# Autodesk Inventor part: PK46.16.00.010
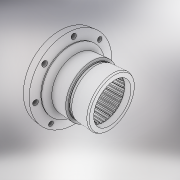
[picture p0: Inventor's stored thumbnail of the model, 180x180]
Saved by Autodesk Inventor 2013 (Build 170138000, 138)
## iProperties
Shininess: 25.0
Length Units: 11269
Angle Units: 11279
Time Units: 11290
Mass Units: 11283
Length Display Precision: 3
Angle Display Precision: 2
Created: 2001-08
Part Number: PK46.16.00.010
Material: Steel, Mild
Document SubType Name: Modeling
Designer: SOleg
Density: 7.86 g/cm^3
Mass: 4404.42 g
Surface Area: 1072.64 cm^2
Volume: 560.359 cm^3
Density: 0.0
Volumn: 0.0
Area: 0.0
PropertySet Name: Model Information
Control State: 0
Master: False
Checked Out: False
Checked Out Date: 2008-10-09
Last Check In Date: 2008-10-09
Author: SOleg
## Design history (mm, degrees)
sketch "Sketch1"
  geometry: L1 (45, 40)-(45, 48.268); L2 (33, 40)-(45, 40); L3 (33, 40.5)-(33, 40); L4 (-22, 40.5)-(33, 40.5); L5 (-22, 35)-(-22, 40.5); L6 (-26, 35)-(-22, 35); L7 (-26, 40)-(-26, 35); L8 (-33, 40)-(-26, 40); L9 (-33, 35)-(-33, 40); L10 (-40, 35)-(-33, 35); L11 (-40, 45)-(-40, 35); L12 (-45, 45)-(-40, 45); L13 (-45, 55)-(-45, 45); L14 (7, 55)-(-45, 55); L15 (7, 49)-(7, 55); L16 (12, 49)-(7, 49); L17 (12, 50)-(12, 49); L18 (42, 50)-(12, 50); L19 (45, 48.268)-(42, 50); L20 (-45, 0)-(45, 0); L21 (-45, 0)-(45, 0)
  constraints: 42 end point, 10 horizontal, 9 vertical, 2 collinear, 1 other
  dimensions: "d1" = 50 vertical distance of L18.start L20.end; "d3" = 40 distance of L1.start L20.end; "d5" = 40.5 vertical distance of L3.start L20.end; "d7" = 35 vertical distance of L5.start L20.start; "d9" = 45 vertical distance of L11.start L20.start; "d11" = 55 distance of L13.start L20.start; "d13" = 67 horizontal distance of L4.start L1.end; "d15" = 12 distance of L2.start L1.start; "d17" = 5 distance of L16.start L15.start; "d19" = 90 horizontal distance of L1.start L12.start; "d23" = 18 horizontal distance of L4.start L10.start; "d25" = 7 distance of L8.start L7.start; "d27" = 7 distance of L10.start L9.start; "d29" = 30 deg angle of L18 L19; "d31" = 3 horizontal distance of L1.end L18.start; "d33" = 49 vertical distance of L16.start L20.end; "d90" = 38 distance between parallel lines of L15 L1
revolve "RevolutionFull1" sketch "Sketch1" stored, may be unused: angle "d34" = 360 deg
workplane "Work Plane1"
node "WorkPlane1"
sketch "Sketch2"
  geometry: L1 (-41.54, -4.27)-(-37.25, -1.145); L2 (-41.54, 4.27)-(-41.54, -4.27); L3 (-37.25, 1.145)-(-41.54, 4.27); L4 (-37.25, -1.145)-(-37.25, 1.145); C1 r 55 at (0, 0) reference; C2 r 35 at (0, 0) reference
  constraints: 8 end point, 2 vertical
  dimensions: "d41" = 8.54 distance of L2.start L1.start; "d43" = 2.29 distance of L1.end L3.start; "d45" = 4.29 horizontal distance of L3.start L2.start; "d47" = 4.27 vertical distance of L1.start C1.centre; "d49" = 1.145 vertical distance of L1.end C2.centre; "d51" = 37.25 horizontal distance of L3.start C2.centre
extrude "ExtrusionBlind1" join sketch "Sketch2" distance "d52" = 55; taper "d53" = 0 deg
node "WorkPlane2"
node "WorkPlane3"
sketch "Sketch3"
  geometry: L1 (18.5, -87.5)-(18.5, -67.5); L2 (32.5, -87.5)-(18.5, -87.5); L3 (32.5, -67.5)-(32.5, -87.5); L4 (28.5, -67.5)-(32.5, -67.5); L5 (28.5, -55)-(28.5, -67.5); L6 (9.283, -55)-(28.5, -55); L7 (16.5, -67.5)-(9.283, -55); L8 (28.5, 45)-(28.5, -45) reference; L9 (23.5, 35)-(23.5, -35) reference; L10 (-184.647, 0)-(153.932, 0); L11 (-61.5, 48.268)-(-61.5, -48.268) reference; L12 (28.5, 55)-(28.5, -55) reference; L13 (28.5, -55)-(-23.5, -55) reference; L14 (28.5, 0)-(80.478, 0); L15 (28.5, -55)-(28.5, -55); L16 (16.5, -67.5)-(18.5, -67.5); L17 (16.5, -67.5)-(18.5, -67.5); L18 (9.283, -55)-(28.5, -55)
  constraints: 27 end point, 3 collinear, 3 horizontal, 3 parallel, 3 vertical, 1 midpoint, 1 perpendicular
  dimensions: "d66" = 14 distance of L2.start L1.start; "d91" = 175 diameter of L2 L10; "d92" = 135 diameter of L4 L10; "d93" = 94 distance between parallel lines of L3 L11; "d94" = 2 distance of L7.start L1.end; "d95" = 135 diameter of L16 L10; "d99" = 4 distance of L4.start L3.start; "d100" = 60 deg angle of L7 L13
revolve "RevolutionAngle1" sketch "Sketch3" stored, may be unused: angle "d69" = 360 deg
workaxis "Work Axis2"
sketch "Sketch7"
  geometry: C1 r 87.5 at (0, 0) reference; C2 r 5 at (0, 77.5)
  constraints: 1 centre point
  dimensions: "d101" = 10 diameter of C2; "d102" = 0 horizontal distance of C1.centre C2.centre; "d103" = 77.5 distance of C1.centre C2.centre
extrude "Extrusion3" cut sketch "Sketch7" stored distance "d104" = 10; taper "d105" = 0 deg
pattern_circular "Circular Pattern3" dims angle "d108" = 360 deg
sketch "Sketch8"
  geometry: L1 (-67.8, 0)-(63.8, 0) reference; L2 (7, 55)-(-45, 55) reference; L3 (7, 49)-(12, 49) reference; L4 (7, 55)-(5, 55); L5 (5, 55)-(5, 50); L6 (5, 50)-(7, 50); L7 (7, 50)-(7, 55); L8 (5, 68)-(5, -68) reference; L9 (12, 50)-(42, 50) reference; 1 further point
  constraints: 10 end point, 2 collinear, 2 parallel, 1 horizontal, 1 perpendicular, 1 vertical, 2 other
revolve "Revolution4" sketch "Sketch8" stored, may be unused: angle "d109" = 90 deg
body "Solid1"
pattern_circular "PolarArray1" dims angle "d56" = 360 deg
other parameters: "d4" = 40.5 (derived), "d6" = 35 (derived), "d8" = 45 (derived), "d10" = 55 (derived), "d12" = 67 (derived), "d14" = 12 (derived), "d16" = 5 (derived), "d20" = 28 (derived), "d22" = 18 (derived), "d24" = 7 (derived), "d26" = 7 (derived), "d28" = 30 deg (derived), "d30" = 3 (derived), "d32" = 49 (derived), "d35" = 0, "d36" = 0, "d37" = 0, "d38" = 0, "d40" = 8.54 (derived), "d42" = 2.29 (derived), "d44" = 4.29 (derived), "d46" = 4.27 (derived), "d48" = 1.145 (derived), "d50" = 37.25 (derived), "d57" = 0, "d58" = -55, "d59" = 4 (derived), "d61" = 1 (derived), "d63" = 12 (derived), "d65" = 17 (derived), "d67" = 75 deg (derived), "d71" = 0, "d72" = 0, "d77" = 14 (derived), "d79" = 102.5 (derived), "d81" = 0 (derived)
